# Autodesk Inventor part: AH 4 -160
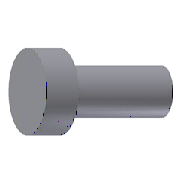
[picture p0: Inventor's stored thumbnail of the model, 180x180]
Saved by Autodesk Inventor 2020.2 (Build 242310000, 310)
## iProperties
Manager: www.cadconsulting.pl
Company: Fabian Stasiak CAD Consulting
Created: 2014-02
Part Number: AH 4 -160
Material: DIN 1.2210
Description: Kołki wypychacza – hartowane
Document SubType Name: Modeling
Standard: DIN 1530/ISO 6751
Designer: F.Stasiak
Standard Revision: 1
Manufacturer: DME
Language: pl-PL
Size Designation: 4 -160
Categories: <MemberInstance><Categories><Category DisplayName="Forma wtryskowa" InternalName="349578f2-f4d4-4954-8c09-8e99297a61c0" Mnemonic="MOLD"><Category DisplayName="K
Mass: 0.191827 g
Surface Area: 2.51725 cm^2
Volume: 0.191827 cm^3
Density: 7.85 g/cm^3
Appearance: Aluminium - ciemne
Catalog Web Link: www.expertbooks.pl
IsCustomPart: 1
Author: F.Stasiak
Subject: Zbiór ćwiczeń. Autodesk Inventor 2020. Kurs Professional
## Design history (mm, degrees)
workplane "Work Plane1"
sketch "Sketch2"
  geometry: L1 (4, -1.5)-(-4, -1.5) reference; L2 (-4, -1.5)-(-4, 1.5) reference; 4 further points
  constraints: 2 midpoint, 1 horizontal alignment, 1 vertical alignment
hole "Otwór ustalający" sketch "Sketch2" at (0, 0) diameter "d44" = 0.55 (derived); stored, may be unused: countersink angle "d48" = 90 deg, drill point angle "d50" = 118 deg; dims "d45" = 6, "d46" = 4, "d47" = 2, "d49" = 0.825 (derived)
sketch "Sketch3"
  geometry: L1 (-2.3, 3.273)-(-2.3, -3.273); A1 r 4 centre (0, 0) between (-2.3, 3.273) and (-2.3, -3.273) reference; 1 further point
  constraints: 2 end point, 2 point on circle, 1 vertical
  dimensions: "d55" = 2.3 distance from line of point (0, 0) L1 (derived)
extrude "Płaszczyzna ustalająca" cut sketch "Sketch3" distance "d42" = 3.3 (derived); taper "d43" = 0 deg
feature "Rzeźbienie1"
body "Solid1"
revolve "Obrót1" stored, may be unused: angle "d11" = 90 deg
fillet "Zaokrąglenie1" dims "d29" = 0.3 (derived)
sketch "Sketch1"
  geometry: L1 (0, 4)-(3, 4); L2 (0, 0)-(0, 4); L3 (3, 2)-(160, 2); L4 (160, 2)-(160, 0); L5 (0, 0)-(160, 0); L6 (3, 4)-(3, 2); 2 further points
  constraints: 12 end point, 4 point on line, 2 horizontal, 2 perpendicular, 1 coincident
  dimensions: "d6" = 3 distance of L1.start L1.end (derived); "d9" = 160 distance between parallel lines of L4 L2 (derived); "d10" = 8 diameter of L1 L5 (derived); "d13" = 4 diameter of L3 L5 (derived)
node "Projected Loop1"
feature "Powierzchnia1"
body "Srf1"
other parameters: "d15" = 0, "d24" = 0, "P" = 4 [user parameter], "T_" = 3 [user parameter], "H_" = 8 [user parameter], "R" = 0.3 [user parameter], "Anti_Rotary_P" = 2.3 [user parameter], "Anti_Rotary_D" = 0.55 [user parameter], "d51" = 0, "d54" = 0, "d56" = 0, "d57" = 0
